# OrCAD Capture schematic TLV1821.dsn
size A3
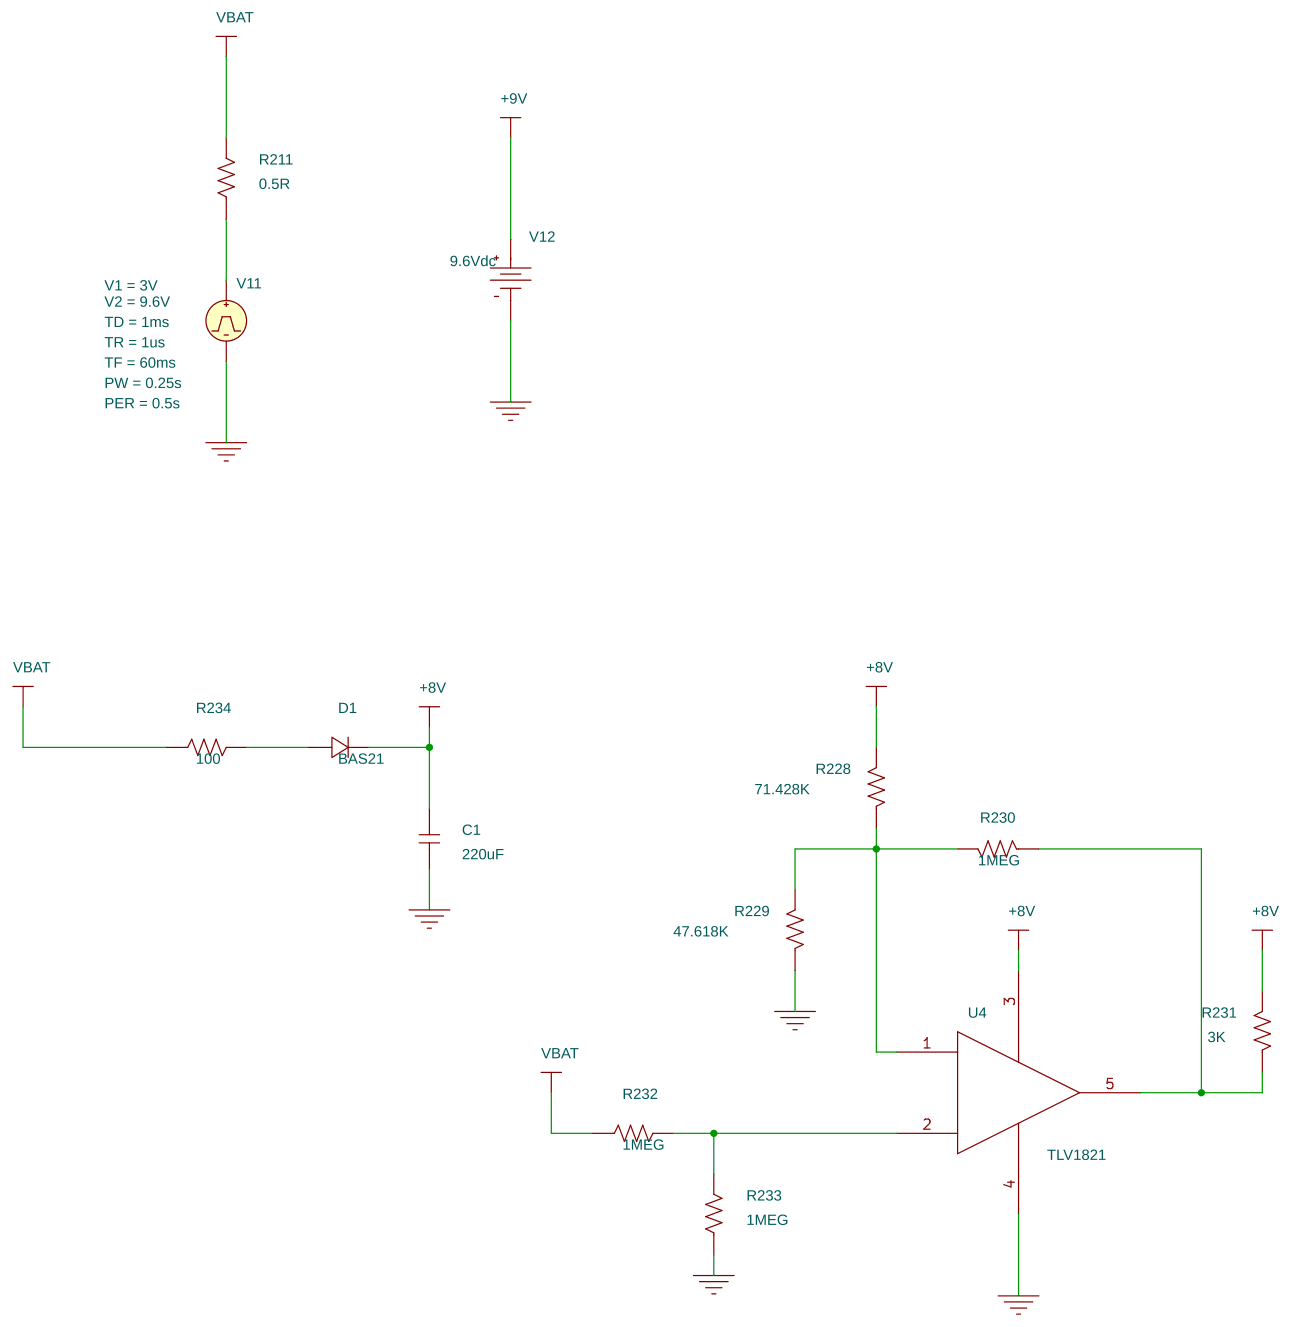
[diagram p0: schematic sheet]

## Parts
C1  220uF  [cap196]
D1  BAS21  [sot23]
R211  0.5R  [AXRC05]
R228  71.428K  [AXRC05]
R229  47.618K  [AXRC05]
R230  1MEG  [AXRC05]
R231  3K  [AXRC05]
R232  1MEG  [AXRC05]
R233  1MEG  [AXRC05]
R234  100  [AXRC05]
U4  TLV1821
V11  VPULSE
V12  VDC

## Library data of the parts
C1 = C
D1 = BAS21
R211 R228-R234 = R
U4 = TLV1821
V11 = VPULSE: PER: 0.5s; PW: 0.25s; TD: 1ms; TF: 60ms; TR: 1us; V1: 3V; V2: 9.6V
V12 = VDC: DC: 9.6Vdc

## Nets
+8V: C1.2 D1.3(2) R228.2 R231.2 U4.3(V+)
+9V: V12.0(+)
VBAT: R211.2 R232.1 R234.1
0: C1.1 R229.1 R233.1 U4.4(V-) V11.2(-) V12.1(-)
N5132688: R211.1 V11.1(+)
N5132866: D1.1 R234.2
N5132918: R228.1 R229.2 R230.2 U4.1(IN+)
N5132962: R230.1 R231.1 U4.5(OUT)
N5133176: R232.2 R233.2 U4.2(IN-)
